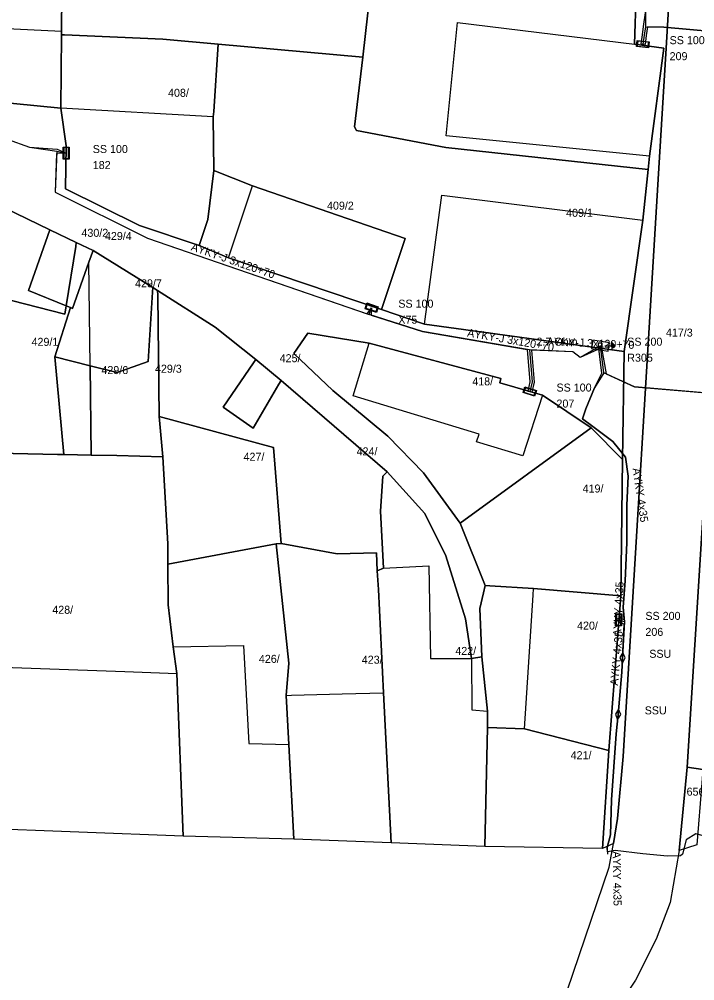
# Model space of a CAD drawing. Extents: x -793400 to -756198, y -1074141 to -1042963.
# Drawn here: x -783545.2 to -783481.9, y -1065400.3 to -1065310.2 of the extents above; entities that cross this region are included whole.
import ezdxf

# ---------------------------------------------------------------- set-up
doc = ezdxf.new("R2010")
doc.units = 0
for name, color, linetype in [('Parcela', 7, 'Continuous'), ('Popiskový text - Parcela', 7, 'Continuous'), ('Popiskový text - PB nn - sk_2 - SJZ', 7, 'Continuous'), ('Popiskový text - Přípojková skříň nn - SJZ', 7, 'Continuous'), ('Popiskový text - Přípojková skříň nn - Typ', 7, 'Continuous'), ('Popiskový text - Rozpojovací skříň nn - SJZ', 7, 'Continuous'), ('Popiskový text - Rozpojovací skříň nn - Typ', 7, 'Continuous'), ('Popiskový text - Spojka nn - Typ', 7, 'Continuous'), ('Popiskový text - Uzemnění - Odpor', 7, 'Continuous'), ('Popiskový text - Vedení nn kabelové', 7, 'Continuous'), ('Skříň', 7, 'Continuous'), ('Spojka nn', 7, 'Continuous'), ('Spojnice nn', 7, 'Continuous'), ('Stavební objekt', 7, 'Continuous'), ('Uzemnění', 7, 'Continuous'), ('Vedení nn kabelové', 7, 'Continuous')]:
    doc.layers.add(name, color=color, linetype=linetype)

msp = doc.modelspace()

# ---------------------------------------------------------------- linework, layer by layer
at = {"layer": 'Parcela'}
for points in [[(-783489.01, -1065251.32), (-783486.18, -1065252.95), (-783483.37, -1065254.95), (-783481.33, -1065256.94), (-783479.03, -1065259.99), (-783477.56, -1065262.77), (-783476.58, -1065265.44), (-783475.97, -1065268.37), (-783475.89, -1065273.94), (-783476.03, -1065276.54), (-783479.07, -1065323.96), (-783482.61, -1065380.27), (-783483.37, -1065388.08), (-783484.21, -1065392.94), (-783485.51, -1065396.38), (-783487.46, -1065400.22), (-783489.74, -1065403.65)], [(-783498.92, -1065416.13), (-783489.9, -1065389.63), (-783489.51, -1065387.41), (-783489.14, -1065385.08), (-783488.6, -1065379.28), (-783485.19, -1065323.12), (-783484.58, -1065312.91), (-783484.23, -1065307.04), (-783483.66, -1065277.28), (-783484.34, -1065273.63), (-783485.45, -1065271.01), (-783485.47, -1065261.82), (-783494.73, -1065261.37), (-783495.96, -1065260.64), (-783500.45, -1065259.14), (-783504.52, -1065258.95), (-783504.29, -1065253.43), (-783507.86, -1065252.91), (-783511.67, -1065253.21), (-783520.08, -1065255.86), (-783523.47, -1065255.09), (-783547.17, -1065255.35), (-783577.61, -1065252.87), (-783589.58, -1065252.19)], [(-783556.53, -1065317.04), (-783541.28, -1065318.54), (-783540.79, -1065322.06), (-783540.86, -1065326.07), (-783533.93, -1065329.53), (-783528.32, -1065331.4), (-783525.57, -1065332.54), (-783511.25, -1065337.4), (-783507.22, -1065338.77), (-783488.52, -1065341.34), (-783488.66, -1065351.43), (-783491.6, -1065348.49), (-783496.17, -1065345.43), (-783500.17, -1065344.25), (-783500.07, -1065343.87), (-783512.41, -1065340.55), (-783518.16, -1065339.62), (-783519.46, -1065341.5), (-783515.82, -1065344.99), (-783510.64, -1065349.26), (-783507.3, -1065352.69), (-783503.88, -1065357.4), (-783501.53, -1065363.26), (-783501.68, -1065363.93), (-783502.02, -1065365.4), (-783501.86, -1065369.94), (-783502.81, -1065370.1), (-783503.37, -1065366.37), (-783505.23, -1065360.48), (-783507.18, -1065356.5), (-783510.7, -1065352.61), (-783520.65, -1065344.03), (-783523.01, -1065342.07), (-783526.83, -1065339.03), (-783532.22, -1065335.61), (-783532.68, -1065335.34), (-783538.26, -1065331.87), (-783539.84, -1065331.11), (-783542.31, -1065329.92), (-783546.57, -1065327.87)], [(-783481.13, -1065380.48), (-783482.61, -1065380.27), (-783479.07, -1065323.96)]]:
    msp.add_lwpolyline(points, dxfattribs=at)
for points in [[(-783484.23, -1065307.04), (-783484.58, -1065312.91), (-783485.19, -1065323.12), (-783488.6, -1065379.28), (-783489.14, -1065385.08), (-783489.51, -1065387.41), (-783490.53, -1065387.88), (-783489.94, -1065378.7), (-783488.81, -1065364.21), (-783488.66, -1065351.43), (-783488.52, -1065341.34), (-783486.76, -1065329.02), (-783486.26, -1065324.26), (-783486.14, -1065323.02), (-783484.78, -1065312.89), (-783487.55, -1065312.54), (-783487.38, -1065307.68), (-783487.11, -1065307.72), (-783486.37, -1065293.56), (-783485.89, -1065277.47), (-783485.45, -1065271.01), (-783484.34, -1065273.63), (-783483.66, -1065277.28)], [(-783504.46, -1065288.79), (-783504.22, -1065292.06), (-783505.83, -1065292.12), (-783505.67, -1065290.16), (-783509.91, -1065289.59), (-783510.91, -1065295.17), (-783512.99, -1065313.76), (-783526.56, -1065312.52), (-783531.73, -1065312.06), (-783540.95, -1065311.67), (-783541.24, -1065311.65), (-783541.22, -1065311.31), (-783541.16, -1065304.39), (-783539.21, -1065301.52), (-783537.61, -1065299.18), (-783533.92, -1065293.77), (-783529.85, -1065287.16), (-783529.96, -1065286.92), (-783530.39, -1065286.07), (-783528.59, -1065286.25), (-783516.9, -1065287.38)], [(-783505.67, -1065290.16), (-783505.83, -1065292.12), (-783504.22, -1065292.06), (-783499.26, -1065291.88), (-783500.57, -1065302.74), (-783496.73, -1065303.2), (-783497.7, -1065306.38), (-783494.79, -1065306.75), (-783487.38, -1065307.68), (-783487.55, -1065312.54), (-783484.78, -1065312.89), (-783486.14, -1065323.02), (-783486.26, -1065324.26), (-783505.21, -1065322.22), (-783513.6, -1065320.63), (-783513.78, -1065320.29), (-783512.99, -1065313.76), (-783510.91, -1065295.17), (-783509.91, -1065289.59)], [(-783571.78, -1065303.16), (-783560.13, -1065304.49), (-783552.66, -1065304.27), (-783552.7, -1065303.7), (-783552.39, -1065303.67), (-783546.16, -1065304.2), (-783541.16, -1065304.39), (-783541.22, -1065311.31), (-783541.24, -1065311.65), (-783541.28, -1065318.54), (-783556.53, -1065317.04), (-783574.41, -1065313.42), (-783576.91, -1065309.57), (-783575.57, -1065302.34)], [(-783527.53, -1065328.95), (-783528.32, -1065331.4), (-783533.93, -1065329.53), (-783540.86, -1065326.07), (-783540.79, -1065322.06), (-783541.28, -1065318.54), (-783541.24, -1065311.65), (-783540.95, -1065311.67), (-783531.73, -1065312.06), (-783526.56, -1065312.52), (-783526.97, -1065318.83), (-783527.01, -1065319.35), (-783526.97, -1065324.36)], [(-783486.76, -1065329.02), (-783488.52, -1065341.34), (-783507.22, -1065338.77), (-783511.25, -1065337.4), (-783509.04, -1065330.74), (-783523.32, -1065325.79), (-783526.97, -1065324.36), (-783527.01, -1065319.35), (-783526.97, -1065318.83), (-783526.56, -1065312.52), (-783512.99, -1065313.76), (-783513.78, -1065320.29), (-783513.6, -1065320.63), (-783505.21, -1065322.22), (-783486.26, -1065324.26)], [(-783542.31, -1065329.92), (-783544.32, -1065335.6), (-783540.78, -1065337.05), (-783540.91, -1065337.84), (-783550.83, -1065335.3), (-783556.72, -1065333.79), (-783559.49, -1065333.28), (-783568.5, -1065333.19), (-783577.94, -1065333.23), (-783578.31, -1065333.24), (-783578.26, -1065328.37), (-783577.34, -1065320.39), (-783564.59, -1065322.15), (-783559.27, -1065323.52), (-783549.65, -1065326.37), (-783546.57, -1065327.87)], [(-783509.04, -1065330.74), (-783511.25, -1065337.4), (-783525.57, -1065332.54), (-783528.32, -1065331.4), (-783527.53, -1065328.95), (-783526.97, -1065324.36), (-783523.32, -1065325.79)], [(-783539.9, -1065331.5), (-783540.78, -1065337.05), (-783544.32, -1065335.6), (-783542.31, -1065329.92), (-783539.84, -1065331.11)], [(-783538.66, -1065332.97), (-783540.21, -1065337.29), (-783540.39, -1065337.21), (-783540.78, -1065337.05), (-783539.9, -1065331.5), (-783539.84, -1065331.11), (-783538.26, -1065331.87), (-783538.31, -1065332.01), (-783538.44, -1065332.36)], [(-783532.71, -1065335.76), (-783533.12, -1065342.25), (-783536, -1065343.29), (-783538.54, -1065342.66), (-783541.86, -1065341.83), (-783540.39, -1065337.21), (-783540.21, -1065337.29), (-783538.66, -1065332.97), (-783538.44, -1065332.36), (-783538.31, -1065332.01), (-783538.26, -1065331.87), (-783532.68, -1065335.34)], [(-783550.83, -1065335.3), (-783540.91, -1065337.84), (-783540.78, -1065337.05), (-783540.39, -1065337.21), (-783541.86, -1065341.83), (-783541, -1065350.97), (-783541.61, -1065350.96), (-783549.93, -1065350.79), (-783552.06, -1065350.81)], [(-783532.21, -1065336.05), (-783532.08, -1065347.43), (-783531.74, -1065351.18), (-783536.05, -1065351.08), (-783538.44, -1065351.03), (-783538.54, -1065342.66), (-783536, -1065343.29), (-783533.12, -1065342.25), (-783532.71, -1065335.76), (-783532.68, -1065335.34), (-783532.22, -1065335.61)], [(-783526.07, -1065346.55), (-783523.26, -1065348.52), (-783520.86, -1065344.39), (-783520.65, -1065344.03), (-783510.7, -1065352.61), (-783511.11, -1065353), (-783511.35, -1065356.29), (-783511.07, -1065361.62), (-783511.64, -1065361.87), (-783511.73, -1065360.19), (-783515.39, -1065360.27), (-783520.65, -1065359.3), (-783521.37, -1065350.31), (-783532.08, -1065347.43), (-783532.21, -1065336.05), (-783532.22, -1065335.61), (-783526.83, -1065339.03), (-783523.01, -1065342.07), (-783523.23, -1065342.39)], [(-783491.6, -1065348.49), (-783503.88, -1065357.4), (-783507.3, -1065352.69), (-783510.64, -1065349.26), (-783515.82, -1065344.99), (-783519.46, -1065341.5), (-783518.16, -1065339.62), (-783512.41, -1065340.55), (-783500.07, -1065343.87), (-783500.17, -1065344.25), (-783496.17, -1065345.43)], [(-783538.54, -1065342.66), (-783538.44, -1065351.03), (-783541, -1065350.97), (-783541.86, -1065341.83)], [(-783520.86, -1065344.39), (-783523.26, -1065348.52), (-783526.07, -1065346.55), (-783523.23, -1065342.39), (-783523.01, -1065342.07), (-783520.65, -1065344.03)], [(-783521.12, -1065359.33), (-783531.26, -1065361.25), (-783531.27, -1065359.96), (-783531.27, -1065359.36), (-783531.74, -1065351.18), (-783532.08, -1065347.43), (-783521.37, -1065350.31), (-783520.65, -1065359.3)], [(-783488.66, -1065351.43), (-783488.81, -1065364.21), (-783496.99, -1065363.53), (-783501.08, -1065363.28), (-783501.53, -1065363.26), (-783503.88, -1065357.4), (-783491.6, -1065348.49)], [(-783530.42, -1065371.49), (-783529.82, -1065386.75), (-783559.2, -1065385.61), (-783558.64, -1065373.74), (-783558.62, -1065373.27), (-783558.55, -1065370.42), (-783558.46, -1065366.76), (-783558.27, -1065359.95), (-783558.01, -1065350.85), (-783552.06, -1065350.81), (-783549.93, -1065350.79), (-783541.61, -1065350.96), (-783541, -1065350.97), (-783538.44, -1065351.03), (-783536.05, -1065351.08), (-783531.74, -1065351.18), (-783531.27, -1065359.36), (-783531.27, -1065359.96), (-783531.26, -1065361.25), (-783531.24, -1065365.05), (-783530.77, -1065368.99)], [(-783503.37, -1065366.37), (-783502.81, -1065370.1), (-783501.86, -1065369.94), (-783501.32, -1065375.01), (-783501.32, -1065376.54), (-783501.56, -1065387.71), (-783510.33, -1065387.35), (-783511.05, -1065373.31), (-783511.54, -1065363.62), (-783511.64, -1065361.87), (-783511.07, -1065361.62), (-783511.35, -1065356.29), (-783511.11, -1065353), (-783510.7, -1065352.61), (-783507.18, -1065356.5), (-783505.23, -1065360.48)], [(-783519.93, -1065378.16), (-783519.47, -1065387.03), (-783529.82, -1065386.75), (-783530.42, -1065371.49), (-783530.77, -1065368.99), (-783531.24, -1065365.05), (-783531.26, -1065361.25), (-783521.12, -1065359.33), (-783519.94, -1065370.53), (-783520.17, -1065373.54)], [(-783520.65, -1065359.3), (-783515.39, -1065360.27), (-783511.73, -1065360.19), (-783511.64, -1065361.87), (-783511.54, -1065363.62), (-783511.05, -1065373.31), (-783510.33, -1065387.35), (-783519.47, -1065387.03), (-783519.93, -1065378.16), (-783520.17, -1065373.54), (-783519.94, -1065370.53), (-783521.12, -1065359.33)], [(-783488.81, -1065364.21), (-783489.94, -1065378.7), (-783497.86, -1065376.69), (-783501.32, -1065376.54), (-783501.32, -1065375.01), (-783501.86, -1065369.94), (-783502.02, -1065365.4), (-783501.68, -1065363.93), (-783501.53, -1065363.26), (-783501.08, -1065363.28), (-783496.99, -1065363.53)], [(-783489.94, -1065378.7), (-783490.53, -1065387.88), (-783501.56, -1065387.71), (-783501.32, -1065376.54), (-783497.86, -1065376.69)], [(-783481.69, -1065387.55), (-783483.37, -1065388.08), (-783482.61, -1065380.27), (-783481.13, -1065380.48), (-783481.23, -1065381.73)]]:
    msp.add_lwpolyline(points, close=True, dxfattribs=at)
at = {"layer": 'Skříň'}
for points in [[(-783487.282, -1065312.195), (-783486.162, -1065312.306), (-783486.218, -1065312.866), (-783487.338, -1065312.754)], [(-783486.224, -1065312.356), (-783487.231, -1065312.256), (-783487.276, -1065312.704), (-783486.268, -1065312.804)], [(-783540.519, -1065322.168), (-783540.519, -1065323.293), (-783541.082, -1065323.292), (-783541.081, -1065322.167)], [(-783540.575, -1065323.236), (-783540.575, -1065322.224), (-783541.025, -1065322.224), (-783541.025, -1065323.236)], [(-783512.619, -1065336.78), (-783511.548, -1065337.125), (-783511.721, -1065337.661), (-783512.792, -1065337.315)], [(-783511.619, -1065337.162), (-783512.583, -1065336.851), (-783512.721, -1065337.279), (-783511.757, -1065337.59)], [(-783489.884, -1065340.503), (-783491.443, -1065340.278), (-783491.556, -1065341.057), (-783489.997, -1065341.282)], [(-783497.804, -1065344.645), (-783496.729, -1065344.978), (-783496.896, -1065345.515), (-783497.97, -1065345.182)], [(-783496.8, -1065345.015), (-783497.767, -1065344.716), (-783497.9, -1065345.145), (-783496.933, -1065345.445)], [(-783489.319, -1065367.023), (-783489.283, -1065365.899), (-783488.721, -1065365.917), (-783488.757, -1065367.041)], [(-783489.229, -1065365.957), (-783489.261, -1065366.969), (-783488.811, -1065366.983), (-783488.779, -1065365.971)]]:
    msp.add_lwpolyline(points, close=True, dxfattribs=at)
at = {"layer": 'Spojka nn'}
for points in [[(-783488.68, -1065370.521), (-783488.406, -1065370.035), (-783488.627, -1065369.523), (-783488.905, -1065370.009)], [(-783489.126, -1065375.823), (-783488.835, -1065375.346), (-783489.039, -1065374.827), (-783489.333, -1065375.303)]]:
    msp.add_lwpolyline(points, close=True, dxfattribs=at)
at = {"layer": 'Spojnice nn'}
for p, q in [((-783541.68, -1065322.57), (-783540.8, -1065322.73)), ((-783512.39, -1065337.87), (-783512.17, -1065337.22)), ((-783490.41, -1065343.32), (-783490.72, -1065340.78)), ((-783488.49, -1065366.65), (-783489.02, -1065366.47)), ((-783488.49, -1065366.65), (-783488.655, -1065370.022))]:
    msp.add_line(p, q, dxfattribs=at)
for points in [[(-783485.48, -1065294.8), (-783486.12, -1065307.93), (-783486.52, -1065309.36), (-783486.52, -1065310.91)], [(-783486.52, -1065310.91), (-783486.63, -1065311.69), (-783486.75, -1065312.53)], [(-783486.52, -1065310.91), (-783484.8, -1065310.95), (-783477.84, -1065311.55), (-783476.96, -1065311.66)], [(-783557.04, -1065317.86), (-783551.91, -1065318.35), (-783548.32, -1065318.93), (-783548.45, -1065320.69), (-783544.23, -1065322.17), (-783541.68, -1065322.57)], [(-783541.68, -1065322.57), (-783541.82, -1065326.39), (-783533.18, -1065330.7), (-783512.39, -1065337.87)], [(-783497.39, -1065341.18), (-783507.4, -1065339.45), (-783512.39, -1065337.87)], [(-783490.72, -1065340.78), (-783492.63, -1065341.89), (-783493.31, -1065341.35), (-783497.39, -1065341.18)], [(-783497.39, -1065341.18), (-783497.14, -1065344.18), (-783497.35, -1065345.08)], [(-783490.41, -1065343.32), (-783491.3, -1065344.72), (-783492.11, -1065346.69), (-783492.41, -1065347.63), (-783491.57, -1065348.25), (-783489.58, -1065349.77), (-783488.39, -1065351.23), (-783488.13, -1065352.99), (-783488.27, -1065355.72), (-783488.27, -1065359.22), (-783488.41, -1065362.82), (-783488.6, -1065365.29), (-783488.49, -1065366.65)], [(-783479.54, -1065345.32), (-783487.55, -1065344.62), (-783490.41, -1065343.32)], [(-783488.655, -1065370.022), (-783488.72, -1065371.36), (-783489.084, -1065375.325)], [(-783489.084, -1065375.325), (-783489.25, -1065377.14), (-783489.69, -1065383.33), (-783489.78, -1065386.6), (-783490.09, -1065387.8), (-783490.08, -1065388.41)]]:
    msp.add_lwpolyline(points, dxfattribs=at)
at = {"layer": 'Stavební objekt'}
for points in [[(-783541.24, -1065311.65), (-783541.28, -1065318.54), (-783556.53, -1065317.04), (-783574.41, -1065313.42), (-783576.91, -1065309.57), (-783575.57, -1065302.34), (-783571.78, -1065303.16), (-783561.7, -1065305.22), (-783556.94, -1065306.21), (-783557.99, -1065310.05), (-783556.6, -1065310.57), (-783541.22, -1065311.31)], [(-783484.78, -1065312.89), (-783486.14, -1065323.02), (-783505.18, -1065321.13), (-783504.14, -1065310.5), (-783487.55, -1065312.54)], [(-783526.97, -1065318.83), (-783527.01, -1065319.35), (-783541.28, -1065318.54), (-783541.24, -1065311.65), (-783540.95, -1065311.67), (-783531.73, -1065312.06), (-783526.56, -1065312.52)], [(-783509.04, -1065330.74), (-783511.25, -1065337.4), (-783525.57, -1065332.54), (-783523.32, -1065325.79)], [(-783486.76, -1065329.02), (-783488.52, -1065341.34), (-783507.22, -1065338.77), (-783505.6, -1065326.67)], [(-783538.66, -1065332.97), (-783540.21, -1065337.29), (-783540.39, -1065337.21), (-783540.78, -1065337.05), (-783544.32, -1065335.6), (-783542.31, -1065329.92), (-783539.84, -1065331.11), (-783538.26, -1065331.87), (-783538.31, -1065332.01), (-783538.44, -1065332.36)], [(-783533.12, -1065342.25), (-783536, -1065343.29), (-783538.54, -1065342.66), (-783538.66, -1065332.97), (-783538.44, -1065332.36), (-783538.31, -1065332.01), (-783538.26, -1065331.87), (-783532.68, -1065335.34), (-783532.71, -1065335.76)], [(-783496.17, -1065345.43), (-783497.99, -1065351.1), (-783502.33, -1065349.78), (-783502.11, -1065349.06), (-783513.9, -1065345.49), (-783512.41, -1065340.55), (-783500.07, -1065343.87), (-783500.17, -1065344.25)], [(-783520.86, -1065344.39), (-783523.26, -1065348.52), (-783526.07, -1065346.55), (-783523.23, -1065342.39), (-783523.01, -1065342.07), (-783520.65, -1065344.03)], [(-783501.32, -1065376.54), (-783501.56, -1065387.71), (-783510.33, -1065387.35), (-783511.05, -1065373.31), (-783511.54, -1065363.62), (-783511.64, -1065361.87), (-783511.07, -1065361.62), (-783506.81, -1065361.42), (-783506.64, -1065370.08), (-783502.81, -1065370.1), (-783502.78, -1065374.89), (-783501.32, -1065375.01)], [(-783488.81, -1065364.21), (-783489.94, -1065378.7), (-783497.86, -1065376.69), (-783497.03, -1065364.17), (-783496.99, -1065363.53)], [(-783519.93, -1065378.16), (-783519.47, -1065387.03), (-783529.82, -1065386.75), (-783530.42, -1065371.49), (-783530.77, -1065368.99), (-783524.18, -1065368.88), (-783523.68, -1065378.06)], [(-783530.42, -1065371.49), (-783529.82, -1065386.75), (-783559.2, -1065385.61), (-783558.64, -1065373.74), (-783558.62, -1065373.27), (-783558.55, -1065370.42), (-783550.26, -1065370.78), (-783535.28, -1065371.32)], [(-783511.05, -1065373.31), (-783510.33, -1065387.35), (-783519.47, -1065387.03), (-783519.93, -1065378.16), (-783520.17, -1065373.54), (-783519.68, -1065373.52), (-783514.94, -1065373.41)], [(-783489.94, -1065378.7), (-783490.53, -1065387.88), (-783501.56, -1065387.71), (-783501.32, -1065376.54), (-783497.86, -1065376.69)]]:
    msp.add_lwpolyline(points, close=True, dxfattribs=at)
at = {"layer": 'Uzemnění'}
for p, q in [((-783490.326, -1065340.78), (-783489.641, -1065340.78)), ((-783489.641, -1065341.126), (-783489.641, -1065340.434)), ((-783489.549, -1065341.001), (-783489.549, -1065340.559)), ((-783489.45, -1065340.924), (-783489.45, -1065340.639)), ((-783489.343, -1065340.832), (-783489.343, -1065340.732))]:
    msp.add_line(p, q, dxfattribs=at)
at = {"layer": 'Vedení nn kabelové'}
for points in [[(-783486.31, -1065294.77), (-783485.49, -1065294.999), (-783486.12, -1065307.93), (-783486.52, -1065309.36), (-783486.718, -1065310.882), (-783486.828, -1065311.662), (-783486.948, -1065312.502), (-783486.75, -1065312.53)], [(-783474.643, -1065322.88), (-783474.643, -1065323.13), (-783474.451, -1065323.13), (-783474.451, -1065322.807), (-783474.4, -1065321.937), (-783474.769, -1065316.452), (-783477.394, -1065314.419), (-783477.159, -1065311.643), (-783477.84, -1065311.55), (-783484.8, -1065310.95), (-783486.319, -1065310.915), (-783486.432, -1065311.718), (-783486.552, -1065312.558), (-783486.75, -1065312.53)], [(-783556.85, -1065316.97), (-783556.84, -1065317.879), (-783551.91, -1065318.35), (-783548.32, -1065318.93), (-783548.45, -1065320.69), (-783544.23, -1065322.17), (-783541.644, -1065322.373), (-783540.8, -1065322.73)], [(-783490.633, -1065340.98), (-783490.197, -1065343.417), (-783487.55, -1065344.62), (-783479.738, -1065345.295), (-783479.219, -1065341.112), (-783478.669, -1065331.413), (-783477.633, -1065322.038), (-783476.1, -1065321.88), (-783475, -1065321.911), (-783475.049, -1065322.773), (-783475.049, -1065323.097), (-783474.543, -1065323.097), (-783474.543, -1065322.88)], [(-783540.8, -1065322.73), (-783541.687, -1065322.772), (-783541.82, -1065326.39), (-783533.18, -1065330.7), (-783512.579, -1065337.805), (-783512.17, -1065337.22)], [(-783512.17, -1065337.22), (-783512.201, -1065337.93), (-783507.4, -1065339.45), (-783497.594, -1065341.145), (-783497.342, -1065344.165), (-783497.545, -1065345.035), (-783497.35, -1065345.08)], [(-783490.633, -1065340.98), (-783492.63, -1065341.89), (-783493.31, -1065341.35), (-783497.189, -1065341.188), (-783496.938, -1065344.195), (-783497.155, -1065345.125), (-783497.35, -1065345.08)], [(-783489.02, -1065366.47), (-783488.956, -1065366.281), (-783488.508, -1065366.433), (-783488.6, -1065365.29), (-783488.41, -1065362.82), (-783488.27, -1065359.22), (-783488.27, -1065355.72), (-783488.13, -1065352.99), (-783488.39, -1065351.23), (-783489.58, -1065349.77), (-783491.57, -1065348.25), (-783492.41, -1065347.63), (-783492.11, -1065346.69), (-783491.3, -1065344.72), (-783490.608, -1065343.344), (-783490.919, -1065340.804), (-783490.919, -1065340.505), (-783490.608, -1065340.505), (-783490.608, -1065340.87)], [(-783488.655, -1065370.022), (-783488.5, -1065366.858), (-783489.084, -1065366.659), (-783489.02, -1065366.47)], [(-783489.084, -1065375.325), (-783488.72, -1065371.36), (-783488.655, -1065370.022)], [(-783479.995, -1065387.71), (-783480.002, -1065387.717), (-783480.002, -1065387.987), (-783480.474, -1065387.987), (-783480.474, -1065386.867), (-783481.793, -1065386.508), (-783482.71, -1065387.076), (-783483.036, -1065388.42), (-783483.219, -1065388.591), (-783484.462, -1065388.6), (-783486.759, -1065388.391), (-783489.355, -1065388.088), (-783490.083, -1065388.208), (-783490.09, -1065387.8), (-783489.78, -1065386.6), (-783489.69, -1065383.33), (-783489.25, -1065377.14), (-783489.084, -1065375.325)]]:
    msp.add_lwpolyline(points, dxfattribs=at)

# ---------------------------------------------------------------- texts
at = {"layer": 'Popiskový text - Parcela'}
for s, p in [('408/', (-783531.247, -1065317.462)), ('409/2', (-783516.351, -1065328.033)), ('409/1', (-783493.948, -1065328.707)), ('430/2', (-783539.362, -1065330.581)), ('429/4', (-783537.159, -1065330.88)), ('429/7', (-783534.334, -1065335.312)), ('417/3', (-783484.595, -1065339.929)), ('429/1', (-783544.035, -1065340.793)), ('425/', (-783520.787, -1065342.329)), ('429/6', (-783537.488, -1065343.44)), ('429/3', (-783532.471, -1065343.313)), ('418/', (-783502.74, -1065344.499)), ('427/', (-783524.172, -1065351.563)), ('424/', (-783513.58, -1065351.057)), ('419/', (-783492.402, -1065354.537)), ('428/', (-783542.093, -1065365.898)), ('420/', (-783492.921, -1065367.381)), ('426/', (-783522.735, -1065370.498)), ('423/', (-783513.094, -1065370.577)), ('422/', (-783504.33, -1065369.754)), ('421/', (-783493.524, -1065379.525))]:
    msp.add_text(s, height=0.75, dxfattribs=at).set_placement(p)
at = {"layer": 'Popiskový text - PB nn - sk_2 - SJZ'}
msp.add_text('656', height=0.75, dxfattribs=at).set_placement((-783482.66, -1065382.94))
at = {"layer": 'Popiskový text - Přípojková skříň nn - SJZ'}
for s, p in [('209', (-783484.25, -1065314.03)), ('182', (-783538.3, -1065324.23)), ('X75', (-783509.67, -1065338.72)), ('207', (-783494.85, -1065346.58)), ('206', (-783486.52, -1065367.97))]:
    msp.add_text(s, height=0.75, dxfattribs=at).set_placement(p)
at = {"layer": 'Popiskový text - Přípojková skříň nn - Typ'}
for s, p in [('SS 100', (-783484.25, -1065312.53)), ('SS 100', (-783538.3, -1065322.73)), ('SS 100', (-783509.67, -1065337.22)), ('SS 100', (-783494.85, -1065345.08)), ('SS 200', (-783486.52, -1065366.47))]:
    msp.add_text(s, height=0.75, dxfattribs=at).set_placement(p)
at = {"layer": 'Popiskový text - Rozpojovací skříň nn - SJZ'}
msp.add_text('R305', height=0.75, dxfattribs=at).set_placement((-783488.22, -1065342.28))
at = {"layer": 'Popiskový text - Rozpojovací skříň nn - Typ'}
msp.add_text('SS 200', height=0.75, dxfattribs=at).set_placement((-783488.22, -1065340.78))
at = {"layer": 'Popiskový text - Spojka nn - Typ'}
for p in [(-783486.155, -1065370.022), (-783486.584, -1065375.325)]:
    msp.add_text('SSU', height=0.75, dxfattribs=at).set_placement(p)
at = {"layer": 'Popiskový text - Uzemnění - Odpor'}
msp.add_text('2.7 Ohm', height=0.75, dxfattribs=at).set_placement((-783496.72, -1065340.78))
at = {"layer": 'Popiskový text - Vedení nn kabelové'}
for s, rotation, p in [('AYKY-J 3x120+70', 340.96718, (-783529.156, -1065331.823)), ('AYKY-J 3x120+70', 350.1918, (-783503.254, -1065339.913)), ('AYKY-J 3x120+70', 357.64026, (-783495.783, -1065340.746)), ('AYKY 4x35', 278.40019, (-783487.728, -1065352.289)), ('AYKY 4x35', 87.20418, (-783488.807, -1065368.02)), ('AYKY 4x35', 84.74046, (-783489.089, -1065372.652)), ('AYKY 4x35', 270.95174, (-783489.584, -1065388.152))]:
    msp.add_text(s, height=0.75, rotation=rotation, dxfattribs=at).set_placement(p)

doc.saveas('drawing.dxf')
